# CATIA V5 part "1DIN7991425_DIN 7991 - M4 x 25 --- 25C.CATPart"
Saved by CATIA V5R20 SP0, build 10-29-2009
Part number: 1DIN7991425_DIN 7991 - M4 x 25 --- 25C
Revision: ANY
Definition: UNKNOWN
Nomenclature: 1DIN7991425_DIN 7991 - M4 x 25 --- 25C
Source: Unknown
Bounding box of the stored display mesh (mm): x 0 to 25, y -3.633 to 3.633, z -3.82 to 3.82
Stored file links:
  C:\Users\Utente\Desktop\IO LAVORO\3D X SITO CF\CUMSA\3D files PO\PO 150425\1DIN7991425_DIN 7991 - M4 x 25 --- 25C.CATPart
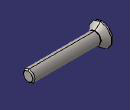
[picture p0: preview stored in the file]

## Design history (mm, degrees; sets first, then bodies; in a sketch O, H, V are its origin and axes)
Body1 "Hex" (main body)
  Solid1: solid without history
